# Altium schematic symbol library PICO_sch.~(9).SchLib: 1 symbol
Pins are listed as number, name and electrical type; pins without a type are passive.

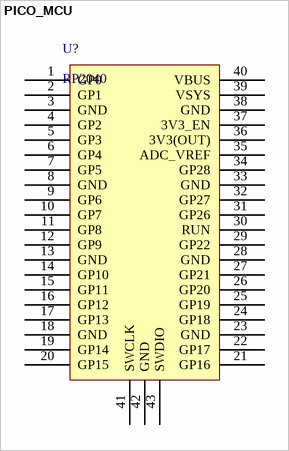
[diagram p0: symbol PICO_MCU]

## PICO_MCU
designator U?, comment RP2040
footprint PCBComponent_1
pins: 1 GP0, 2 GP1, 3 GND, 4 GP2, 5 GP3, 6 GP4, 7 GP5, 8 GND, 9 GP6, 10 GP7, 11 GP8, 12 GP9, 13 GND, 14 GP10, 15 GP11, 16 GP12, 17 GP13, 18 GND, 19 GP14, 20 GP15, 21 GP16, 22 GP17, 23 GND, 24 GP18, 25 GP19, 26 GP20, 27 GP21, 28 GND, 29 GP22, 30 RUN, 31 GP26, 32 GP27, 33 GND, 34 GP28, 35 ADC_VREF, 36 3V3(OUT), 37 3V3_EN, 38 GND, 39 VSYS, 40 VBUS, 41 SWCLK, 42 GND, 43 SWDIO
